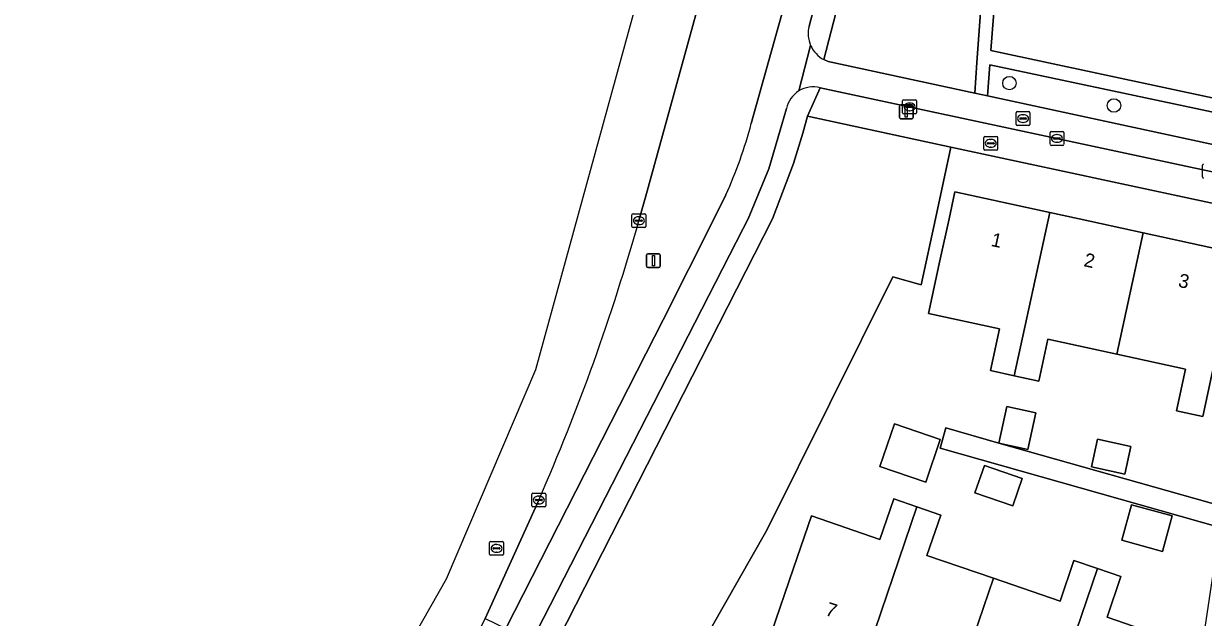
# Model space of a CAD drawing. Extents: x 162661 to 163484, y 380247 to 381230.
# Drawn here: x 163062.4 to 163147.9, y 380971.1 to 381014.2 of the extents above; entities that cross this region are included whole.
import ezdxf

# ---------------------------------------------------------------- set-up
doc = ezdxf.new("R2010")
doc.units = 0
for name, color, linetype in [('IMGEO_Berm_groen', 7, 'Continuous'), ('IMGEO_Boom', 7, 'Continuous'), ('IMGEO_Brandkraan', 7, 'Continuous'), ('IMGEO_Erf', 7, 'Continuous'), ('IMGEO_Fietspad_open', 7, 'Continuous'), ('IMGEO_Gemengd_bos', 7, 'Continuous'), ('IMGEO_Groenvoorziening', 7, 'Continuous'), ('IMGEO_Kolk', 7, 'Continuous'), ('IMGEO_Lichtmast', 7, 'Continuous'), ('IMGEO_Loofbos', 7, 'Continuous'), ('IMGEO_Pand', 7, 'Continuous'), ('IMGEO_Pand_nummerreeks', 7, 'Continuous'), ('IMGEO_Rijbaan_lokaal_gesloten', 7, 'Continuous'), ('IMGEO_Rioolput', 7, 'Continuous'), ('IMGEO_Voetpad_open', 7, 'Continuous')]:
    doc.layers.add(name, color=color, linetype=linetype)

msp = doc.modelspace()

# ---------------------------------------------------------------- linework, layer by layer
at = {"layer": 'IMGEO_Berm_groen'}
for points in [[(163120.641, 381044.463), (163121.552, 381047.782), (163120.284, 381048.133), (163107.445, 381001.581), (163106.974, 380999.872)], [(163115.123, 381006.913), (163118.605, 381019.439)], [(163099.718, 380979.621), (163095.831, 380971.041), (163097.334, 380970.302), (163108.722, 380992.689), (163112.397, 380999.985), (163113.278, 381001.751)]]:
    msp.add_lwpolyline(points, dxfattribs=at)
for centre, radius, start, end in [((163082.973, 381015.493), 33.276, 335.60731, 345.05692), ((162957.438, 381042.026), 155.364, 336.31746, 344.257)]:
    msp.add_arc(centre, radius, start, end, dxfattribs=at)
at = {"layer": 'IMGEO_Boom'}
for centre in [(163133.834, 381009.843), (163141.412, 381008.219)]:
    msp.add_circle(centre, 0.489, dxfattribs=at)
at = {"layer": 'IMGEO_Brandkraan'}
for p, q in [((163131.981, 381005.052), (163131.981, 381005.904)), ((163132.056, 381005.978), (163132.908, 381005.978)), ((163132.469, 381005.758), (163132.494, 381005.758)), ((163132.982, 381005.904), (163132.982, 381005.052)), ((163132.908, 381004.978), (163132.056, 381004.978)), ((163132.24, 381005.472), (163132.24, 381005.484)), ((163132.678, 381005.435), (163132.28, 381005.435)), ((163132.283, 381005.521), (163132.681, 381005.521)), ((163132.492, 381005.198), (163132.467, 381005.198)), ((163132.724, 381005.484), (163132.724, 381005.472))]:
    msp.add_line(p, q, dxfattribs=at)
for points in [[(163131.981, 381005.052), (163131.981, 381005.904)], [(163132.056, 381005.978), (163132.908, 381005.978)], [(163132.982, 381005.904), (163132.982, 381005.052)], [(163132.908, 381004.978), (163132.056, 381004.978)]]:
    msp.add_lwpolyline(points, dxfattribs=at)
for centre, radius, start, end in [((163132.058, 381005.902), 0.0765, 91.55205, 178.44795), ((163132.058, 381005.902), 0.0765, 91.55205, 178.44795), ((163132.906, 381005.902), 0.0765, 1.55205, 88.44795), ((163132.906, 381005.902), 0.0765, 1.55205, 88.44795), ((163132.058, 381005.054), 0.0765, 181.55205, 268.44795), ((163132.058, 381005.054), 0.0765, 181.55205, 268.44795), ((163132.28, 381005.481), 0.0403, 85.87752, 175.75265), ((163132.277, 381005.471), 0.0366, 178.93798, 274.71019), ((163132.681, 381005.478), 0.043, 264.86636, 352.45326), ((163132.685, 381005.483), 0.0386, 1.73085, 96.63898), ((163132.906, 381005.054), 0.0765, 271.55205, 358.44795), ((163132.906, 381005.054), 0.0765, 271.55205, 358.44795)]:
    msp.add_arc(centre, radius, start, end, dxfattribs=at)
for centre, major_axis, ratio, start_param, end_param in [((163132.468, 381005.478), (-0.387, 0.002), 0.722429, 4.712389, 7.853982), ((163132.493, 381005.478), (-0.39, 0.002), 0.717154, 1.570796, 4.712389)]:
    msp.add_ellipse(centre, major_axis=major_axis, ratio=ratio, start_param=start_param, end_param=end_param, dxfattribs=at)
at = {"layer": 'IMGEO_Erf'}
for points in [[(163162.414, 381026.565), (163162.279, 381026.698), (163154.328, 381046.987), (163144.896, 381043.328), (163143.928, 381045.981), (163137.766, 381042.44), (163133.585, 381040.037), (163133.484, 381038.184), (163132.855, 381030.173), (163133.892, 381030.091), (163132.494, 381012.197), (163152.72, 381007.872), (163152.681, 381007.77), (163154.245, 381007.436), (163154.323, 381007.677)], [(163149.428, 381000.936), (163129.592, 381005.204), (163128.473, 381000), (163127.445, 380995.227), (163125.384, 380995.798), (163116.243, 380977.443), (163111.192, 380968.563), (163145.977, 380956.699), (163149.106, 380977.626), (163128.816, 380983.375), (163129.235, 380984.855), (163133.069, 380983.733), (163149.335, 380979.16), (163152.054, 380997.345)]]:
    msp.add_lwpolyline(points, dxfattribs=at)
for points in [[(163136.624, 380991.28), (163135.968, 380988.247), (163134.188, 380988.633), (163132.466, 380989.006), (163133.121, 380992.04), (163127.975, 380993.154), (163128.825, 380997.076), (163129.458, 381000), (163129.882, 381001.962), (163136.765, 381000.462), (163138.884, 381000), (163143.527, 380998.988), (163150.404, 380997.489), (163147.846, 380985.674), (163145.948, 380986.085), (163146.605, 380989.119), (163141.613, 380990.2)], [(163133.069, 380983.733), (163133.649, 380986.397), (163135.753, 380985.938), (163135.173, 380983.275)], [(163124.448, 380982.059), (163125.501, 380985.135), (163128.819, 380984.001), (163127.767, 380980.924)], [(163139.794, 380982.03), (163140.226, 380984.026), (163142.642, 380983.503), (163142.21, 380981.506)], [(163131.338, 380980.147), (163132.016, 380982.128), (163134.77, 380981.186), (163134.093, 380979.205)], [(163138.51, 380975.232), (163140.218, 380974.648), (163141.917, 380974.067), (163140.91, 380971.123), (163145.878, 380969.423), (163142.982, 380960.951), (163136.323, 380963.22), (163129.779, 380965.45), (163123.232, 380967.681), (163116.569, 380969.952), (163118.188, 380974.683), (163119.483, 380978.469), (163124.45, 380976.769), (163125.453, 380979.702), (163127.133, 380979.127), (163128.859, 380978.536), (163127.855, 380975.602), (163132.676, 380973.953), (163137.508, 380972.3)], [(163141.972, 380976.708), (163142.681, 380979.285), (163145.633, 380978.473), (163144.924, 380975.896)]]:
    msp.add_lwpolyline(points, close=True, dxfattribs=at)
at = {"layer": 'IMGEO_Fietspad_open'}
for points in [[(163119.312, 381013.978), (163119.808, 381015.8), (163120.674, 381019.048), (163121.368, 381023.659), (163120.959, 381033.122)], [(163118.662, 381019.652), (163118.605, 381019.439), (163115.123, 381006.913)], [(163119.424, 381012.577), (163118.572, 381009.273)], [(163118.572, 381009.273), (163119.424, 381012.577)], [(163132.234, 381008.915), (163131.32, 381009.112), (163120.698, 381011.403), (163120.376, 381011.544)], [(163120.113, 381009.509), (163156.555, 381001.7), (163157.083, 381005.414)], [(163154.844, 381004.039), (163153.517, 381004.326), (163132.234, 381008.915)], [(163114.537, 380999.295), (163114.897, 381000), (163116.385, 381003.634), (163117.342, 381006.837), (163117.677, 381007.997)], [(163113.278, 381001.751), (163112.397, 380999.985), (163108.722, 380992.689), (163097.334, 380970.302), (163085.202, 380946.557), (163081.312, 380939.161), (163078.602, 380941.045)], [(163078.572, 380932.781), (163078.201, 380932.005), (163077.707, 380931.721), (163077.359, 380931.919), (163078.839, 380929.669), (163080.32, 380932.543), (163082.573, 380934.938), (163082.967, 380936.912), (163083.252, 380937.877), (163083.627, 380938.938), (163084.062, 380939.851), (163114.537, 380999.295)]]:
    msp.add_lwpolyline(points, dxfattribs=at)
for centre, radius, start, end in [((163121.388, 381013.439), 2.145, 165.44629, 203.69506), ((163121.396, 381013.439), 2.152, 203.61372, 241.71284), ((163119.616, 381007.589), 1.982, 121.79575, 168.1118), ((163119.618, 381007.592), 1.98, 75.52354, 121.89054), ((163082.973, 381015.493), 33.276, 335.60731, 345.05692)]:
    msp.add_arc(centre, radius, start, end, dxfattribs=at)
at = {"layer": 'IMGEO_Gemengd_bos'}
msp.add_lwpolyline([(163101.756, 380970.755), (163101.103, 380969.474), (163106.127, 380966.443), (163109.929, 380965.978), (163111.192, 380968.563), (163116.243, 380977.443), (163125.384, 380995.798), (163127.445, 380995.227), (163128.473, 381000), (163129.592, 381005.204), (163119.2, 381007.44), (163118.862, 381006.215), (163118.19, 381004.006), (163116.667, 381000)], close=True, dxfattribs=at)
at = {"layer": 'IMGEO_Groenvoorziening'}
msp.add_lwpolyline([(163153.99, 381006.544), (163152.581, 381006.881), (163132.406, 381011.17), (163132.234, 381008.915), (163153.517, 381004.326)], close=True, dxfattribs=at)
at = {"layer": 'IMGEO_Kolk'}
for p, q in [((163126.094, 381007.695), (163126.094, 381008.547)), ((163126.169, 381008.621), (163127.021, 381008.621)), ((163126.582, 381008.401), (163126.607, 381008.401)), ((163127.095, 381008.547), (163127.095, 381007.695)), ((163127.021, 381007.621), (163126.169, 381007.621)), ((163126.353, 381008.115), (163126.353, 381008.127)), ((163126.791, 381008.078), (163126.393, 381008.078)), ((163126.396, 381008.164), (163126.794, 381008.164)), ((163126.605, 381007.841), (163126.58, 381007.841)), ((163126.837, 381008.127), (163126.837, 381008.115)), ((163136.78, 381005.405), (163136.78, 381006.257)), ((163136.855, 381006.331), (163137.707, 381006.331)), ((163137.039, 381005.825), (163137.039, 381005.837)), ((163137.477, 381005.788), (163137.079, 381005.788)), ((163137.082, 381005.874), (163137.48, 381005.874)), ((163137.268, 381006.111), (163137.293, 381006.111)), ((163137.523, 381005.837), (163137.523, 381005.825)), ((163137.781, 381006.257), (163137.781, 381005.405)), ((163137.707, 381005.331), (163136.855, 381005.331)), ((163137.291, 381005.551), (163137.266, 381005.551)), ((163147.822, 381003.039), (163147.822, 381003.891)), ((163106.473, 380999.446), (163106.473, 381000.298)), ((163106.548, 381000.372), (163107.4, 381000.372)), ((163106.732, 380999.866), (163106.732, 380999.878)), ((163107.17, 380999.829), (163106.772, 380999.829)), ((163106.775, 380999.915), (163107.173, 380999.915)), ((163106.961, 381000.152), (163106.986, 381000.152)), ((163107.216, 380999.878), (163107.216, 380999.866)), ((163107.474, 381000.298), (163107.474, 380999.446)), ((163107.4, 380999.372), (163106.548, 380999.372)), ((163106.984, 380999.592), (163106.959, 380999.592)), ((163099.217, 380979.195), (163099.217, 380980.047)), ((163099.292, 380980.121), (163100.144, 380980.121)), ((163100.218, 380980.047), (163100.218, 380979.195)), ((163100.144, 380979.121), (163099.292, 380979.121)), ((163099.476, 380979.615), (163099.476, 380979.627)), ((163099.914, 380979.578), (163099.516, 380979.578)), ((163099.519, 380979.664), (163099.917, 380979.664)), ((163099.728, 380979.341), (163099.703, 380979.341)), ((163099.705, 380979.901), (163099.73, 380979.901)), ((163099.96, 380979.627), (163099.96, 380979.615))]:
    msp.add_line(p, q, dxfattribs=at)
for points in [[(163126.094, 381007.695), (163126.094, 381008.547)], [(163126.169, 381008.621), (163127.021, 381008.621)], [(163127.095, 381008.547), (163127.095, 381007.695)], [(163127.021, 381007.621), (163126.169, 381007.621)], [(163136.78, 381005.405), (163136.78, 381006.257)], [(163136.855, 381006.331), (163137.707, 381006.331)], [(163137.781, 381006.257), (163137.781, 381005.405)], [(163137.707, 381005.331), (163136.855, 381005.331)], [(163147.822, 381003.039), (163147.822, 381003.891)], [(163106.473, 380999.446), (163106.473, 381000.298)], [(163106.548, 381000.372), (163107.4, 381000.372)], [(163107.474, 381000.298), (163107.474, 380999.446)], [(163107.4, 380999.372), (163106.548, 380999.372)], [(163099.217, 380979.195), (163099.217, 380980.047)], [(163099.292, 380980.121), (163100.144, 380980.121)], [(163100.218, 380980.047), (163100.218, 380979.195)], [(163100.144, 380979.121), (163099.292, 380979.121)]]:
    msp.add_lwpolyline(points, dxfattribs=at)
for centre, radius, start, end in [((163126.171, 381008.545), 0.0765, 91.55205, 178.44795), ((163126.171, 381008.545), 0.0765, 91.55205, 178.44795), ((163127.019, 381008.545), 0.0765, 1.55205, 88.44795), ((163127.019, 381008.545), 0.0765, 1.55205, 88.44795), ((163126.171, 381007.697), 0.0765, 181.55205, 268.44795), ((163126.171, 381007.697), 0.0765, 181.55205, 268.44795), ((163126.393, 381008.124), 0.0403, 85.87752, 175.75265), ((163126.39, 381008.114), 0.0366, 178.93798, 274.71019), ((163126.794, 381008.121), 0.043, 264.86636, 352.45326), ((163126.798, 381008.126), 0.0386, 1.73085, 96.63898), ((163127.019, 381007.697), 0.0765, 271.55205, 358.44795), ((163127.019, 381007.697), 0.0765, 271.55205, 358.44795), ((163136.857, 381006.255), 0.0765, 91.55205, 178.44795), ((163136.857, 381006.255), 0.0765, 91.55205, 178.44795), ((163137.079, 381005.834), 0.0403, 85.87752, 175.75265), ((163137.076, 381005.824), 0.0366, 178.93798, 274.71019), ((163137.48, 381005.831), 0.043, 264.86636, 352.45326), ((163137.484, 381005.836), 0.0386, 1.73085, 96.63898), ((163137.705, 381006.255), 0.0765, 1.55205, 88.44795), ((163137.705, 381006.255), 0.0765, 1.55205, 88.44795), ((163136.857, 381005.407), 0.0765, 181.55205, 268.44795), ((163136.857, 381005.407), 0.0765, 181.55205, 268.44795), ((163137.705, 381005.407), 0.0765, 271.55205, 358.44795), ((163137.705, 381005.407), 0.0765, 271.55205, 358.44795), ((163147.899, 381003.889), 0.0765, 91.55205, 178.44795), ((163147.899, 381003.889), 0.0765, 91.55205, 178.44795), ((163147.899, 381003.041), 0.0765, 181.55205, 268.44795), ((163147.899, 381003.041), 0.0765, 181.55205, 268.44795), ((163106.55, 381000.296), 0.0765, 91.55205, 178.44795), ((163106.55, 381000.296), 0.0765, 91.55205, 178.44795), ((163106.772, 380999.875), 0.0403, 85.87752, 175.75265), ((163106.769, 380999.865), 0.0366, 178.93798, 274.71019), ((163107.173, 380999.872), 0.043, 264.86636, 352.45326), ((163107.177, 380999.877), 0.0386, 1.73085, 96.63898), ((163107.398, 381000.296), 0.0765, 1.55205, 88.44795), ((163107.398, 381000.296), 0.0765, 1.55205, 88.44795), ((163106.55, 380999.448), 0.0765, 181.55205, 268.44795), ((163106.55, 380999.448), 0.0765, 181.55205, 268.44795), ((163107.398, 380999.448), 0.0765, 271.55205, 358.44795), ((163107.398, 380999.448), 0.0765, 271.55205, 358.44795), ((163099.294, 380980.045), 0.0765, 91.55205, 178.44795), ((163099.294, 380980.045), 0.0765, 91.55205, 178.44795), ((163100.142, 380980.045), 0.0765, 1.55205, 88.44795), ((163100.142, 380980.045), 0.0765, 1.55205, 88.44795), ((163099.294, 380979.197), 0.0765, 181.55205, 268.44795), ((163099.294, 380979.197), 0.0765, 181.55205, 268.44795), ((163099.516, 380979.624), 0.0403, 85.87752, 175.75265), ((163099.513, 380979.614), 0.0366, 178.93798, 274.71019), ((163099.917, 380979.621), 0.043, 264.86636, 352.45326), ((163099.921, 380979.626), 0.0386, 1.73085, 96.63898), ((163100.142, 380979.197), 0.0765, 271.55205, 358.44795), ((163100.142, 380979.197), 0.0765, 271.55205, 358.44795)]:
    msp.add_arc(centre, radius, start, end, dxfattribs=at)
for centre, major_axis, ratio, start_param, end_param in [((163126.581, 381008.121), (-0.387, 0.002), 0.722429, 4.712389, 7.853982), ((163126.606, 381008.121), (-0.39, 0.002), 0.717154, 1.570796, 4.712389), ((163137.267, 381005.831), (-0.387, 0.002), 0.722429, 4.712389, 7.853982), ((163137.292, 381005.831), (-0.39, 0.002), 0.717154, 1.570796, 4.712389), ((163106.96, 380999.872), (-0.387, 0.002), 0.722429, 4.712389, 7.853982), ((163106.985, 380999.872), (-0.39, 0.002), 0.717154, 1.570796, 4.712389), ((163099.704, 380979.621), (-0.387, 0.002), 0.722429, 4.712389, 7.853982), ((163099.729, 380979.621), (-0.39, 0.002), 0.717154, 1.570796, 4.712389)]:
    msp.add_ellipse(centre, major_axis=major_axis, ratio=ratio, start_param=start_param, end_param=end_param, dxfattribs=at)
at = {"layer": 'IMGEO_Lichtmast'}
for p, q in [((163125.96, 381008.261), (163126.75, 381008.261)), ((163126.75, 381008.261), (163125.96, 381008.261)), ((163125.86, 381007.361), (163125.86, 381008.161)), ((163125.86, 381008.161), (163125.86, 381007.361)), ((163126.85, 381008.161), (163126.85, 381007.361)), ((163126.85, 381007.361), (163126.85, 381008.161)), ((163126.75, 381007.261), (163125.96, 381007.261)), ((163125.96, 381007.261), (163126.75, 381007.261)), ((163107.528, 380996.572), (163107.528, 380997.372)), ((163107.528, 380997.372), (163107.528, 380996.572)), ((163107.628, 380997.472), (163108.418, 380997.472)), ((163108.418, 380997.472), (163107.628, 380997.472)), ((163108.518, 380997.372), (163108.518, 380996.572)), ((163108.518, 380996.572), (163108.518, 380997.372)), ((163108.418, 380996.472), (163107.628, 380996.472)), ((163107.628, 380996.472), (163108.418, 380996.472))]:
    msp.add_line(p, q, dxfattribs=at)
for points in [[(163126.28, 381008.136), (163126.43, 381008.136), (163126.43, 381007.386), (163126.28, 381007.386), (163126.28, 381008.136)], [(163107.948, 380997.347), (163108.098, 380997.347), (163108.098, 380996.597), (163107.948, 380996.597), (163107.948, 380997.347)]]:
    msp.add_lwpolyline(points, dxfattribs=at)
for centre, start, end in [((163125.96, 381008.161), 90, 180), ((163125.96, 381008.161), 90, 180), ((163126.75, 381008.161), 0, 90), ((163126.75, 381008.161), 360, 90), ((163125.96, 381007.361), 180, 270), ((163125.96, 381007.361), 180, 270), ((163126.75, 381007.361), 270, 0), ((163126.75, 381007.361), 270, 0), ((163107.628, 380997.372), 90, 180), ((163107.628, 380997.372), 90, 180), ((163108.418, 380997.372), 0, 90), ((163108.418, 380997.372), 360, 90), ((163107.628, 380996.572), 180, 270), ((163107.628, 380996.572), 180, 270), ((163108.418, 380996.572), 270, 0), ((163108.418, 380996.572), 270, 0)]:
    msp.add_arc(centre, 0.1, start, end, dxfattribs=at)
at = {"layer": 'IMGEO_Loofbos'}
msp.add_lwpolyline([(163122.628, 381032.986), (163122.859, 381028.94), (163122.945, 381023.45), (163122.156, 381018.381), (163120.376, 381011.544), (163120.698, 381011.403), (163131.32, 381009.112), (163131.483, 381011.348), (163132.855, 381030.173)], dxfattribs=at)
at = {"layer": 'IMGEO_Pand'}
for points in [[(163134.188, 380988.633), (163136.765, 381000.462), (163129.882, 381001.962), (163129.458, 381000), (163128.825, 380997.076), (163127.975, 380993.154), (163133.121, 380992.04), (163132.466, 380989.006)], [(163141.613, 380990.2), (163143.527, 380998.988), (163138.884, 381000), (163136.765, 381000.462), (163134.188, 380988.633), (163135.968, 380988.247), (163136.624, 380991.28)], [(163141.613, 380990.2), (163146.605, 380989.119), (163145.948, 380986.085), (163147.846, 380985.674), (163150.404, 380997.489), (163143.527, 380998.988)], [(163133.069, 380983.733), (163135.173, 380983.275), (163135.753, 380985.938), (163133.649, 380986.397)], [(163124.448, 380982.059), (163127.767, 380980.924), (163128.819, 380984.001), (163125.501, 380985.135)], [(163139.794, 380982.03), (163142.21, 380981.506), (163142.642, 380983.503), (163140.226, 380984.026)], [(163131.338, 380980.147), (163134.093, 380979.205), (163134.77, 380981.186), (163132.016, 380982.128)], [(163123.232, 380967.681), (163127.133, 380979.127), (163125.453, 380979.702), (163124.45, 380976.769), (163119.483, 380978.469), (163118.188, 380974.683), (163116.569, 380969.952)], [(163132.676, 380973.953), (163127.855, 380975.602), (163128.859, 380978.536), (163127.133, 380979.127), (163123.232, 380967.681), (163129.779, 380965.45)], [(163141.972, 380976.708), (163144.924, 380975.896), (163145.633, 380978.473), (163142.681, 380979.285)], [(163136.323, 380963.22), (163140.218, 380974.648), (163138.51, 380975.232), (163137.508, 380972.3), (163132.676, 380973.953), (163129.779, 380965.45)], [(163136.323, 380963.22), (163142.982, 380960.951), (163145.878, 380969.423), (163140.91, 380971.123), (163141.917, 380974.067), (163140.218, 380974.648)]]:
    msp.add_lwpolyline(points, close=True, dxfattribs=at)
at = {"layer": 'IMGEO_Rijbaan_lokaal_gesloten'}
for points in [[(163106.974, 380999.872), (163107.445, 381001.581), (163120.284, 381048.133), (163142.304, 381127.974), (163143.035, 381130.883), (163143.543, 381132.838), (163140.547, 381133.584), (163139.069, 381133.952), (163135.379, 381116.471), (163114.525, 381043.88), (163099.48, 380989.07), (163092.997, 380973.876), (163069.643, 380932.768), (163062.369, 380926.22)], [(163092.842, 380964.895), (163095.831, 380971.041), (163099.718, 380979.621)]]:
    msp.add_lwpolyline(points, dxfattribs=at)
msp.add_arc((162957.438, 381042.026), 155.364, 336.31746, 344.257, dxfattribs=at)
at = {"layer": 'IMGEO_Rioolput'}
for p, q in [((163134.321, 381006.848), (163134.321, 381007.7)), ((163134.396, 381007.774), (163135.248, 381007.774)), ((163134.809, 381007.554), (163134.834, 381007.554)), ((163135.322, 381007.7), (163135.322, 381006.848)), ((163135.248, 381006.774), (163134.396, 381006.774)), ((163134.58, 381007.268), (163134.58, 381007.28)), ((163135.018, 381007.231), (163134.62, 381007.231)), ((163134.623, 381007.317), (163135.021, 381007.317)), ((163134.832, 381006.994), (163134.807, 381006.994)), ((163135.064, 381007.28), (163135.064, 381007.268)), ((163096.154, 380975.69), (163096.154, 380976.542)), ((163096.229, 380976.616), (163097.081, 380976.616)), ((163097.155, 380976.542), (163097.155, 380975.69)), ((163096.413, 380976.11), (163096.413, 380976.122)), ((163096.851, 380976.073), (163096.453, 380976.073)), ((163096.456, 380976.159), (163096.854, 380976.159)), ((163096.665, 380975.836), (163096.64, 380975.836)), ((163096.642, 380976.396), (163096.667, 380976.396)), ((163096.897, 380976.122), (163096.897, 380976.11)), ((163097.081, 380975.616), (163096.229, 380975.616))]:
    msp.add_line(p, q, dxfattribs=at)
for points in [[(163134.321, 381006.848), (163134.321, 381007.7)], [(163134.396, 381007.774), (163135.248, 381007.774)], [(163135.322, 381007.7), (163135.322, 381006.848)], [(163135.248, 381006.774), (163134.396, 381006.774)], [(163096.154, 380975.69), (163096.154, 380976.542)], [(163096.229, 380976.616), (163097.081, 380976.616)], [(163097.155, 380976.542), (163097.155, 380975.69)], [(163097.081, 380975.616), (163096.229, 380975.616)]]:
    msp.add_lwpolyline(points, dxfattribs=at)
for centre, radius, start, end in [((163134.398, 381007.698), 0.0765, 91.55205, 178.44795), ((163134.398, 381007.698), 0.0765, 91.55205, 178.44795), ((163135.246, 381007.698), 0.0765, 1.55205, 88.44795), ((163135.246, 381007.698), 0.0765, 1.55205, 88.44795), ((163134.398, 381006.85), 0.0765, 181.55205, 268.44795), ((163134.398, 381006.85), 0.0765, 181.55205, 268.44795), ((163134.62, 381007.277), 0.0403, 85.87752, 175.75265), ((163134.617, 381007.267), 0.0366, 178.93798, 274.71019), ((163135.021, 381007.274), 0.043, 264.86636, 352.45326), ((163135.025, 381007.279), 0.0386, 1.73085, 96.63898), ((163135.246, 381006.85), 0.0765, 271.55205, 358.44795), ((163135.246, 381006.85), 0.0765, 271.55205, 358.44795), ((163096.231, 380976.54), 0.0765, 91.55205, 178.44795), ((163096.231, 380976.54), 0.0765, 91.55205, 178.44795), ((163097.079, 380976.54), 0.0765, 1.55205, 88.44795), ((163097.079, 380976.54), 0.0765, 1.55205, 88.44795), ((163096.231, 380975.692), 0.0765, 181.55205, 268.44795), ((163096.231, 380975.692), 0.0765, 181.55205, 268.44795), ((163096.453, 380976.119), 0.0403, 85.87752, 175.75265), ((163096.45, 380976.109), 0.0366, 178.93798, 274.71019), ((163096.854, 380976.116), 0.043, 264.86636, 352.45326), ((163096.858, 380976.121), 0.0386, 1.73085, 96.63898), ((163097.079, 380975.692), 0.0765, 271.55205, 358.44795), ((163097.079, 380975.692), 0.0765, 271.55205, 358.44795)]:
    msp.add_arc(centre, radius, start, end, dxfattribs=at)
for centre, major_axis, ratio, start_param, end_param in [((163134.808, 381007.274), (-0.387, 0.002), 0.722429, 4.712389, 7.853982), ((163134.833, 381007.274), (-0.39, 0.002), 0.717154, 1.570796, 4.712389), ((163096.641, 380976.116), (-0.387, 0.002), 0.722429, 4.712389, 7.853982), ((163096.666, 380976.116), (-0.39, 0.002), 0.717154, 1.570796, 4.712389)]:
    msp.add_ellipse(centre, major_axis=major_axis, ratio=ratio, start_param=start_param, end_param=end_param, dxfattribs=at)
at = {"layer": 'IMGEO_Voetpad_open'}
for points in [[(163120.959, 381033.122), (163121.368, 381023.659), (163120.674, 381019.048), (163119.808, 381015.8), (163119.312, 381013.978)], [(163120.376, 381011.544), (163122.156, 381018.381), (163122.945, 381023.45), (163122.859, 381028.94), (163122.628, 381032.986)], [(163116.667, 381000), (163118.19, 381004.006), (163118.862, 381006.215), (163119.2, 381007.44), (163120.113, 381009.509)], [(163155.712, 380996.349), (163156.288, 381000), (163156.555, 381001.7), (163120.113, 381009.509), (163119.2, 381007.44), (163129.592, 381005.204), (163149.428, 381000.936)], [(163117.677, 381007.997), (163117.342, 381006.837), (163116.385, 381003.634), (163114.897, 381000), (163114.537, 380999.295), (163084.062, 380939.851), (163083.627, 380938.938), (163083.252, 380937.877), (163082.967, 380936.912), (163082.573, 380934.938), (163084.365, 380935.219)], [(163085.075, 380938.231), (163085.699, 380939.507), (163101.103, 380969.474), (163101.756, 380970.755), (163116.667, 381000)]]:
    msp.add_lwpolyline(points, dxfattribs=at)
for points in [[(163131.32, 381009.112), (163132.234, 381008.915), (163132.406, 381011.17), (163152.581, 381006.881), (163153.99, 381006.544), (163154.245, 381007.436), (163152.681, 381007.77), (163152.72, 381007.872), (163132.494, 381012.197), (163133.892, 381030.091), (163132.855, 381030.173), (163131.483, 381011.348)], [(163133.069, 380983.733), (163129.235, 380984.855), (163128.816, 380983.375), (163149.106, 380977.626), (163149.335, 380979.16)]]:
    msp.add_lwpolyline(points, close=True, dxfattribs=at)
for centre, radius, start, end in [((163121.388, 381013.439), 2.145, 165.44629, 203.69506), ((163121.396, 381013.439), 2.152, 203.61372, 241.71284), ((163119.616, 381007.589), 1.982, 121.79575, 168.1118), ((163119.618, 381007.592), 1.98, 75.52354, 121.89054)]:
    msp.add_arc(centre, radius, start, end, dxfattribs=at)

# ---------------------------------------------------------------- texts
at = {"layer": 'IMGEO_Pand_nummerreeks'}
for s, rotation, p in [('1', 347.70364, (163132.447, 380998.046)), ('2', 347.70364, (163139.174, 380996.58)), ('3', 347.70364, (163146.016, 380995.088)), ('7', 341.18196, (163120.423, 380971.302))]:
    msp.add_text(s, height=1, rotation=rotation, dxfattribs=at).set_placement(p)

doc.saveas('drawing.dxf')
